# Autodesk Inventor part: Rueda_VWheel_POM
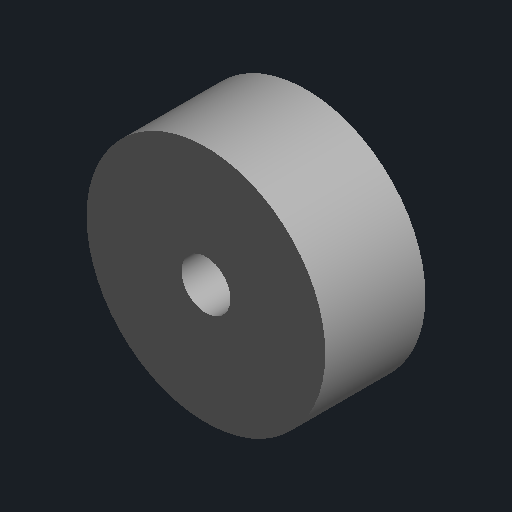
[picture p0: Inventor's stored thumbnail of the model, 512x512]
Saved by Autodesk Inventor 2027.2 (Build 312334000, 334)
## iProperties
Part Number: Rueda_VWheel_POM
Material: Genérico
Document SubType Name: Modelado
Designer: Usuario
Appearance: Por defecto
Author: Usuario
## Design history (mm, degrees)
sketch "Boceto1"
  geometry: C1 r 12.195 at (0, 0); C2 r 2.5 at (0, 0)
  constraints: 2 centre point
  dimensions: "d0" = 10.23 dimension on C1.centre C1 C2.centre C2
extrude "Extrusión1" new body sketch "Boceto1" stored distance "d0" = 10.23; taper "d1" = 0 deg
node "Sólido1"
node "Cuerpos sólidos"
node "Cuerpos de superficie"
